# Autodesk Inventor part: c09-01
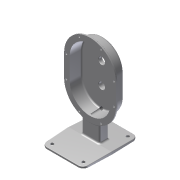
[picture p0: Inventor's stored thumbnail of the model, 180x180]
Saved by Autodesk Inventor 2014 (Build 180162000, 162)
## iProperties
Created: 2010-12
Part Number: c09-01
Document SubType Name: Modeling
Designer: Thom Tremblay
Density: 7.25 g/cm^3
Material: Iron, Cast
Mass: 1233.53 g
Surface Area: 883.619 cm^2
Volume: 170.142 cm^3
Appearance: Steel
Author: Thom Tremblay
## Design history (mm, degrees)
sketch "Sketch1"
  geometry: L1 (-50, -50)-(-50, 0); L2 (50, 0)-(50, -50); L3 (-60, 0)-(-60, -50); L4 (60, -50)-(60, 0); A1 r 50 centre (0, 0) between (50, 0) and (-50, 0); A2 r 50 centre (0, -50) between (-50, -50) and (50, -50); A3 r 60 centre (0, -50) between (-60, -50) and (60, -50); A4 r 60 centre (0, 0) between (60, 0) and (-60, 0); 1 further point
  constraints: 8 end point, 8 point on circle, 4 centre point, 4 tangent, 2 parallel, 1 coincident, 1 vertical, 3 other
  dimensions: "d0" = 50 distance of L2.start L2.end; "d1" = 50 radius of A1; "d2" = 10 radial gap between concentric circles of A4 A1
extrude "Extrusion1" new body sketch "Sketch1" distance "d3" = 30; taper "d4" = -2 deg
fillet "Fillet1" dims "d7" = 6
shell "Shell3" dims "d132" = 3
extrude "Extrusion2" join sketch "Sketch1" distance "d5" = 4; taper "d6" = -2 deg
fillet "Fillet12" dims "d133" = 2
fillet "Fillet13" dims "d134" = 1
workplane "Work Plane2"
sketch "Sketch7"
  geometry: C1 r 7.5 at (0, -95); 1 further point
  constraints: 1 centre point, 1 vertical alignment
  dimensions: "d64" = 15 diameter of C1; "d65" = 95 distance of point (0, 0) C1.centre
extrude "Extrusion8" join sketch "Sketch7" stored distance "d66" = 12.7; taper "d67" = 2 deg
fillet "Fillet2" dims "d9" = 3, "d10" = 1
hole "Hole3" diameter "d70" = 8; stored, may be unused: countersink angle "d74" = 82 deg, drill point angle "d76" = 118 deg; dims "d68" = 10, "d69" = 10, "d71" = 9, "d72" = 9.525, "d73" = 6.35, "d75" = 30, "d77" = 0.62479, "d78" = 7.985
workplane "Work Plane1"
sketch "Sketch2"
  geometry: L1 (-20.917, -1.5)-(20.917, -1.5); L2 (20.917, -1.5)-(20.219, -21.5); L3 (20.219, -21.5)-(16.219, -21.5); L4 (16.219, -21.5)-(15.695, -6.5); L5 (15.695, -6.5)-(-15.695, -6.5); L6 (-15.695, -6.5)-(-16.219, -21.5); L7 (-16.219, -21.5)-(-20.219, -21.5); L8 (-20.219, -21.5)-(-20.917, -1.5); L9 (-16.219, -21.5)-(16.219, -21.5); 3 further points
  constraints: 18 end point, 3 parallel, 2 equal length, 2 midpoint, 2 vertical alignment, 1 collinear, 1 horizontal
  dimensions: "d12" = 4 deg angle of L8 L6; "d13" = 88 deg angle of L8 L1; "d14" = 1.5 distance from line of point (0, 0) L1; "d15" = 20 vertical distance of L1.end L2.end; "d16" = 4 distance of L2.end L3.end; "d17" = 5 distance between parallel lines of L1 L5
extrude "Extrusion3" join sketch "Sketch2" stored distance "d18" = 27.94; taper "d19" = 0 deg
sketch "Sketch3"
  geometry: L1 (-70, -150)-(70, -150) reference; L2 (-50, -150)-(50, -150); L3 (50, -150)-(50, -144); L4 (50, -144)-(-50, -144); L5 (-50, -144)-(-50, -150); 2 further points
  constraints: 8 end point, 2 parallel, 1 horizontal, 1 midpoint, 1 perpendicular, 1 point on line, 1 vertical alignment
  dimensions: "d20" = 100 distance of L3.end L4.end; "d21" = 6 distance of L2.end L3.end
extrude "Extrusion4" join sketch "Sketch3" distance "d22" = 63.5; taper "d23" = 0 deg
feature "FaceDraft1" dims angle "d24" = 2 deg
sketch "Sketch4"
  geometry: L1 (-50, -150)-(50, -150) reference; L2 (50, -150)-(50, -143.773) reference; L3 (50, -143.773)-(-50, -143.773) reference; L4 (-50, -143.773)-(-50, -150) reference; 1 further point
extrude "Extrusion5" join sketch "Sketch4" distance "d25" = 63.5; taper "d26" = 0 deg
feature "FaceDraft2" dims angle "d27" = 2 deg
fillet "Fillet3" dims "d28" = 12
fillet "Fillet4"
fillet "Fillet5"
fillet "Fillet6" dims "d29" = 4
fillet "Fillet7" dims "d30" = 4
fillet "Fillet8" dims "d31" = 2
sketch "Sketch5"
  geometry: C1 r 12.5 at (0, 0); 1 further point
  constraints: 1 centre point, 1 coincident
  dimensions: "d32" = 25 diameter of C1
extrude "Extrusion6" join sketch "Sketch5" distance "d33" = 5; taper "d35" = -2 deg; dims "d34" = 8, "d36" = -2 deg
hole "Hole1" diameter "d40" = 14; stored, may be unused: countersink angle "d44" = 82 deg, drill point angle "d46" = 118 deg; dims "d38" = 10, "d39" = 10, "d41" = 19.05, "d42" = 9.525, "d43" = 6.35, "d45" = 25.4
sketch "Sketch10"
  geometry: C1 r 12.5 at (0, -50); A1 r 60 centre (0, -50) between (-60, -50) and (-18.704, -107.01) reference; 1 further point
  constraints: 1 centre point, 1 coincident
  dimensions: "d135" = 25 diameter of C1
extrude "Extrusion9" join sketch "Sketch10" distance "d136" = 12; taper "d137" = -2 deg
fillet "Fillet9" dims "d37" = 3
hole "Hole2" diameter "d55" = 14; stored, may be unused: countersink angle "d59" = 82 deg, drill point angle "d61" = 118 deg; dims "d53" = 10, "d54" = 10, "d56" = 19.05, "d57" = 9.525, "d58" = 6.35, "d60" = 8
hole "Hole4" diameter "d81" = 7; stored, may be unused: countersink angle "d85" = 82 deg, drill point angle "d87" = 118 deg; dims "d79" = 10, "d80" = 10, "d82" = 12.7, "d83" = 12.8778, "d84" = 6.35, "d86" = 30.48
hole "Hole5" diameter "d90" = 7; stored, may be unused: countersink angle "d94" = 82 deg, drill point angle "d96" = 118 deg; dims "d88" = 10, "d89" = 10, "d91" = 12.7, "d92" = 12.8778, "d93" = 6.35, "d95" = 30.48
hole "Hole6" diameter "d99" = 7; stored, may be unused: countersink angle "d103" = 82 deg, drill point angle "d105" = 118 deg; dims "d97" = 10, "d98" = 10, "d100" = 12.7, "d101" = 12.8778, "d102" = 6.35, "d104" = 30.48
hole "Hole7" diameter "d108" = 7; stored, may be unused: countersink angle "d112" = 82 deg, drill point angle "d114" = 118 deg; dims "d106" = 10, "d107" = 10, "d109" = 12.7, "d110" = 12.8778, "d111" = 6.35, "d113" = 30.48
fillet "Fillet11" dims "d122" = 1
chamfer "Chamfer1" distance "d138" = 1; stored, may be unused: second distance "d139" = 2, angle "d140" = 45 deg
node "Hole11"
body "Solid1"
node "Projected Loop1"
sketch "Sketch11"
  geometry: 8 further points
hole "Hole10" sketch "Sketch11" diameter "d141" = 4.5; stored, may be unused: countersink angle "d145" = 90 deg, drill point angle "d147" = 0 deg; dims "d142" = 6, "d143" = 4, "d144" = 2, "d146" = 8
other parameters: "d63" = -35
